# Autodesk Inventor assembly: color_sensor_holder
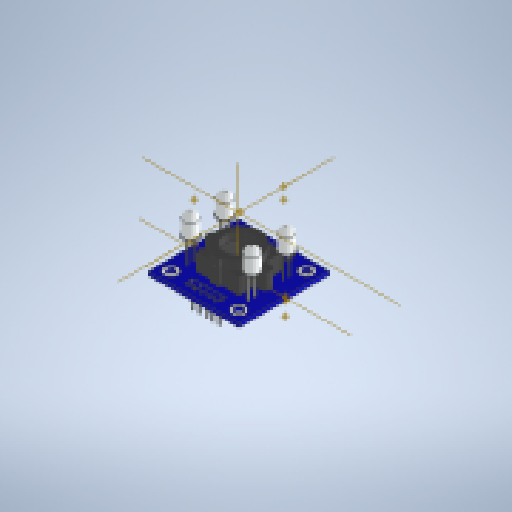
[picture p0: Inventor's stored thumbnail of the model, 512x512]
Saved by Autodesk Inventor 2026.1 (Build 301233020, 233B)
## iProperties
Created: 2026-10
Part Number: color_sensor_holder
Document SubType Name: Assembly
Designer: alolo
Author: alolo
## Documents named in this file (2)
- C:\Users\hp\Documents\Inventor\DOM1_CartesianRobot\color_sensor_holder.iam
- C:\Users\hp\Documents\Inventor\DOM1_CartesianRobot\TCS3200 Color Sensor Module.ipt
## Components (1 placed, 1 different names)
1. TCS3200 Color Sensor Module:1 — Mate:13, Mate:33, Mate:34, Mate:35, Mate:36
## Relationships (5: Mate 5)
- Mate:13: TCS3200 Color Sensor Module:1
- Mate:33: TCS3200 Color Sensor Module:1
- Mate:34: TCS3200 Color Sensor Module:1
- Mate:35: TCS3200 Color Sensor Module:1
- Mate:36: TCS3200 Color Sensor Module:1
